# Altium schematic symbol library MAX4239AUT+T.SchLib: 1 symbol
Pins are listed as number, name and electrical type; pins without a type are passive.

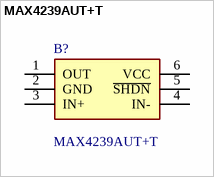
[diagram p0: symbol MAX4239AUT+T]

## MAX4239AUT+T
designator B?
MAXIM INTEGRATED PRODUCTS - MAX4239AUT+T - OP AMP, 6.5MHZ, 1.6V/US, SOT23-6; Manufacturer_Name: Analog Devices; Geometry.Height: 1.45mm
footprint SOT95P280X145-6N
pins: 1 OUT, 2 GND, 3 IN+, 4 IN-, 5 ~{SHDN}, 6 VCC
